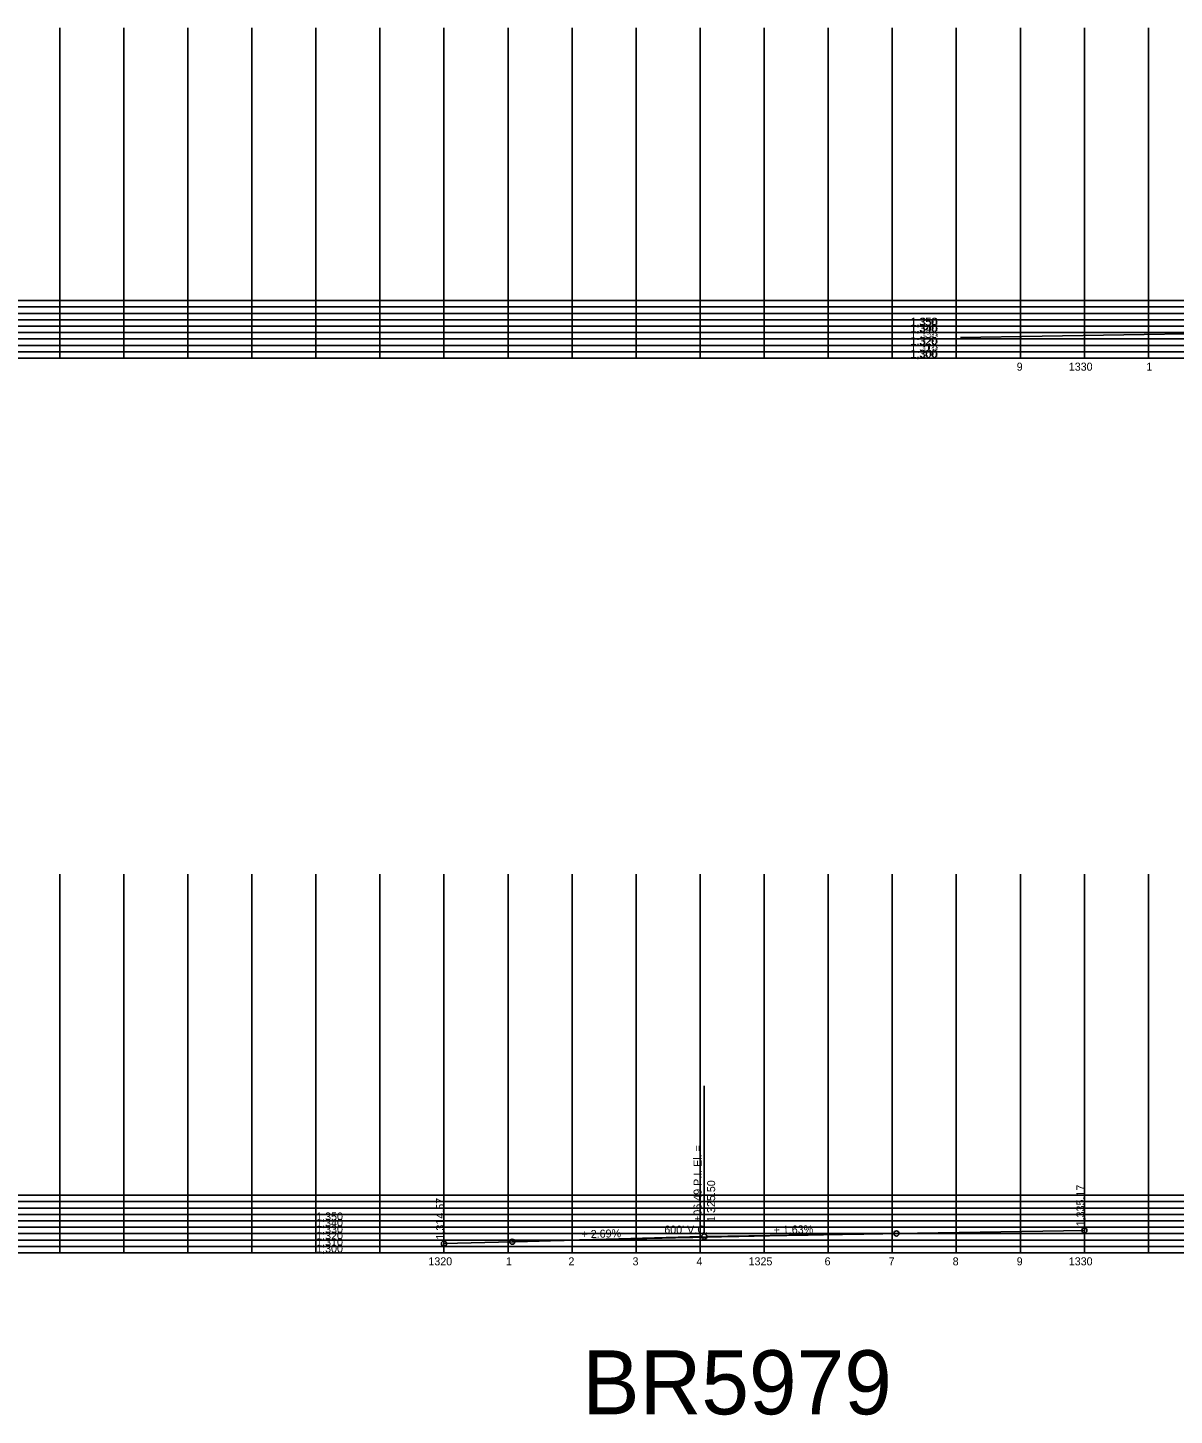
# Model space of a CAD drawing. Extents: x 680639 to 702326, y 743523 to 756592.
# Drawn here: x 687576 to 689366, y 743523 to 745690 of the extents above; entities that cross this region are included whole.
import ezdxf

# ---------------------------------------------------------------- set-up
doc = ezdxf.new("R2010")
doc.units = 0
for name, color, linetype in [('Default', 7, 'Continuous'), ('R_Grid', 7, 'Continuous'), ('R_Proposed Road', 7, 'Continuous')]:
    doc.layers.add(name, color=color, linetype=linetype)

msp = doc.modelspace()

# ---------------------------------------------------------------- linework, layer by layer
at = {"layer": 'Default'}
for p, q in [((689032.2, 745206.1), (689462.2, 745213.1)), ((680725.7, 745174), (702325.7, 745174)), ((688632.2, 743806.2), (688632.2, 744037.6)), ((688225.7, 743791.2), (688332.2, 743794.1)), ((688332.2, 743794.1), (688628.2, 743802)), ((688932.2, 743807), (688636.2, 743802.2)), ((688932.2, 743807), (689225.7, 743811.8)), ((680725.7, 743776.7), (702325.7, 743776.7))]:
    msp.add_line(p, q, dxfattribs=at)
for centre in [(689225.7, 743811.8), (688225.7, 743791.2), (688332.2, 743794.1), (688632.2, 743802.2), (688932.2, 743807)]:
    msp.add_circle(centre, 4, dxfattribs=at)
msp.add_spline([(688332.2, 743794.1), (688344.2, 743794.4), (688356.2, 743794.7), (688368.2, 743795), (688380.2, 743795.4), (688392.2, 743795.7), (688404.2, 743796), (688416.2, 743796.3), (688428.2, 743796.6), (688440.2, 743796.9), (688452.2, 743797.2), (688464.2, 743797.5), (688476.2, 743797.8), (688488.2, 743798.1), (688500.2, 743798.4), (688512.2, 743798.6), (688524.2, 743798.9), (688536.2, 743799.2), (688548.2, 743799.5), (688560.2, 743799.8), (688572.2, 743800), (688584.2, 743800.3), (688596.2, 743800.6), (688608.2, 743800.8), (688620.2, 743801.1), (688632.2, 743801.4), (688644.2, 743801.6), (688656.2, 743801.9), (688668.2, 743802.1), (688680.2, 743802.4), (688692.2, 743802.6), (688704.2, 743802.9), (688716.2, 743803.1), (688728.2, 743803.4), (688740.2, 743803.6), (688752.2, 743803.8), (688764.2, 743804.1), (688776.2, 743804.3), (688788.2, 743804.5), (688800.2, 743804.7), (688812.2, 743805), (688824.2, 743805.2), (688836.2, 743805.4), (688848.2, 743805.6), (688860.2, 743805.8), (688872.2, 743806), (688884.2, 743806.2), (688896.2, 743806.4), (688908.2, 743806.6), (688920.2, 743806.8), (688932.2, 743807)], degree=3, dxfattribs=at)
at = {"layer": 'R_Grid'}
for p, q in [((687625.7, 745174), (687625.7, 745690.1)), ((687725.7, 745174), (687725.7, 745690.1)), ((687825.7, 745174), (687825.7, 745690.1)), ((687925.7, 745174), (687925.7, 745690.1)), ((688025.7, 745174), (688025.7, 745690.1)), ((688125.7, 745174), (688125.7, 745690.1)), ((688225.7, 745174), (688225.7, 745690.1)), ((688325.7, 745174), (688325.7, 745690.1)), ((688425.7, 745174), (688425.7, 745690.1)), ((688525.7, 745174), (688525.7, 745690.1)), ((688625.7, 745174), (688625.7, 745690.1)), ((688725.7, 745174), (688725.7, 745690.1)), ((688825.7, 745174), (688825.7, 745690.1)), ((688925.7, 745174), (688925.7, 745690.1)), ((689025.7, 745174), (689025.7, 745690.1)), ((689125.7, 745174), (689125.7, 745690.1)), ((689225.7, 745174), (689225.7, 745690.1)), ((689325.7, 745174), (689325.7, 745690.1)), ((680725.7, 745264), (695445.5, 745264)), ((680725.7, 745254), (695445.5, 745254)), ((680725.7, 745244), (695445.5, 745244)), ((680725.7, 745234), (695445.5, 745234)), ((680725.7, 745224), (695445.5, 745224)), ((680725.7, 745214), (695445.5, 745214)), ((680725.7, 745204), (695445.5, 745204)), ((680725.7, 745194), (695445.5, 745194)), ((680725.7, 745184), (695445.5, 745184)), ((680725.7, 745174), (695445.5, 745174)), ((687625.7, 743776.7), (687625.7, 744368.3)), ((687725.7, 743776.7), (687725.7, 744368.3)), ((687825.7, 743776.7), (687825.7, 744368.3)), ((687925.7, 743776.7), (687925.7, 744368.3)), ((688025.7, 743776.7), (688025.7, 744368.3)), ((688125.7, 743776.7), (688125.7, 744368.3)), ((688225.7, 743776.7), (688225.7, 744368.3)), ((688325.7, 743776.7), (688325.7, 744368.3)), ((688425.7, 743776.7), (688425.7, 744368.3)), ((688525.7, 743776.7), (688525.7, 744368.3)), ((688625.7, 743776.7), (688625.7, 744368.3)), ((688725.7, 743776.7), (688725.7, 744368.3)), ((688825.7, 743776.7), (688825.7, 744368.3)), ((688925.7, 743776.7), (688925.7, 744368.3)), ((689025.7, 743776.7), (689025.7, 744368.3)), ((689125.7, 743776.7), (689125.7, 744368.3)), ((689225.7, 743776.7), (689225.7, 744368.3)), ((689325.7, 743776.7), (689325.7, 744368.3)), ((680725.7, 743866.7), (694315.6, 743866.7)), ((680725.7, 743856.7), (694315.6, 743856.7)), ((680725.7, 743846.7), (694315.6, 743846.7)), ((680725.7, 743836.7), (694315.6, 743836.7)), ((680725.7, 743826.7), (694315.6, 743826.7)), ((680725.7, 743816.7), (694315.6, 743816.7)), ((680725.7, 743806.7), (694315.6, 743806.7)), ((680725.7, 743796.7), (694315.6, 743796.7)), ((680725.7, 743786.7), (694315.6, 743786.7)), ((680725.7, 743776.7), (694315.6, 743776.7))]:
    msp.add_line(p, q, dxfattribs=at)

# ---------------------------------------------------------------- texts
at = {"layer": 'Default'}
for s, p in [('1,350', (688953.9, 745224.6)), ('1,340', (688953.9, 745214.6)), ('1,350', (688954, 745224.6)), ('1,340', (688954, 745214.6)), ('1,350', (688954.1, 745224.6)), ('1,340', (688954.1, 745214.6)), ('1,350', (688954.2, 745224.6)), ('1,350', (688954.3, 745224.6)), ('1,340', (688954.2, 745214.6)), ('1,340', (688954.3, 745214.6)), ('1,350', (688954.4, 745224.6)), ('1,340', (688954.4, 745214.6)), ('1,350', (688954.4, 745224.6)), ('1,340', (688954.4, 745214.6)), ('1,350', (688954.5, 745224.6)), ('1,340', (688954.5, 745214.6)), ('1,350', (688954.6, 745224.6)), ('1,340', (688954.6, 745214.6)), ('1,350', (688954.7, 745224.6)), ('1,350', (688954.8, 745224.6)), ('1,340', (688954.7, 745214.6)), ('1,340', (688954.8, 745214.6)), ('1,350', (688954.9, 745224.6)), ('1,340', (688954.9, 745214.6)), ('1,350', (688954.9, 745224.6)), ('1,340', (688954.9, 745214.6)), ('1,350', (688955, 745224.6)), ('1,340', (688955, 745214.6)), ('1,350', (688955.1, 745224.6)), ('1,340', (688955.1, 745214.6)), ('1,350', (688955.2, 745224.6)), ('1,350', (688955.3, 745224.6)), ('1,340', (688955.2, 745214.6)), ('1,340', (688955.3, 745214.6)), ('1,350', (688955.4, 745224.6)), ('1,340', (688955.4, 745214.6)), ('1,350', (688955.4, 745224.6)), ('1,340', (688955.4, 745214.6)), ('1,350', (688955.5, 745224.6)), ('1,340', (688955.5, 745214.6)), ('1,330', (688953.9, 745204.6)), ('1,320', (688953.9, 745194.6)), ('1,330', (688954, 745204.6)), ('1,320', (688954, 745194.6)), ('1,330', (688954.1, 745204.6)), ('1,320', (688954.1, 745194.6)), ('1,330', (688954.2, 745204.6)), ('1,330', (688954.3, 745204.6)), ('1,320', (688954.2, 745194.6)), ('1,320', (688954.3, 745194.6)), ('1,330', (688954.4, 745204.6)), ('1,320', (688954.4, 745194.6)), ('1,330', (688954.4, 745204.6)), ('1,320', (688954.4, 745194.6)), ('1,330', (688954.5, 745204.6)), ('1,320', (688954.5, 745194.6)), ('1,330', (688954.6, 745204.6)), ('1,320', (688954.6, 745194.6)), ('1,330', (688954.7, 745204.6)), ('1,330', (688954.8, 745204.6)), ('1,320', (688954.7, 745194.6)), ('1,320', (688954.8, 745194.6)), ('1,330', (688954.9, 745204.6)), ('1,320', (688954.9, 745194.6)), ('1,330', (688954.9, 745204.6)), ('1,320', (688954.9, 745194.6)), ('1,330', (688955, 745204.6)), ('1,320', (688955, 745194.6)), ('1,330', (688955.1, 745204.6)), ('1,320', (688955.1, 745194.6)), ('1,330', (688955.2, 745204.6)), ('1,330', (688955.3, 745204.6)), ('1,320', (688955.2, 745194.6)), ('1,320', (688955.3, 745194.6)), ('1,330', (688955.4, 745204.6)), ('1,320', (688955.4, 745194.6)), ('1,330', (688955.4, 745204.6)), ('1,320', (688955.4, 745194.6)), ('1,330', (688955.5, 745204.6)), ('1,320', (688955.5, 745194.6)), ('1,310', (688953.9, 745184.6)), ('1,300', (688953.9, 745174.6)), ('1,310', (688954, 745184.6)), ('1,300', (688954, 745174.6)), ('1,310', (688954.1, 745184.6)), ('1,300', (688954.1, 745174.6)), ('1,310', (688954.2, 745184.6)), ('1,310', (688954.3, 745184.6)), ('1,300', (688954.2, 745174.6)), ('1,300', (688954.3, 745174.6)), ('1,310', (688954.4, 745184.6)), ('1,300', (688954.4, 745174.6)), ('1,310', (688954.4, 745184.6)), ('1,300', (688954.4, 745174.6)), ('1,310', (688954.5, 745184.6)), ('1,300', (688954.5, 745174.6)), ('1,310', (688954.6, 745184.6)), ('1,300', (688954.6, 745174.6)), ('1,310', (688954.7, 745184.6)), ('1,310', (688954.8, 745184.6)), ('1,300', (688954.7, 745174.6)), ('1,300', (688954.8, 745174.6)), ('1,310', (688954.9, 745184.6)), ('1,300', (688954.9, 745174.6)), ('1,310', (688954.9, 745184.6)), ('1,300', (688954.9, 745174.6)), ('1,310', (688955, 745184.6)), ('1,300', (688955, 745174.6)), ('1,310', (688955.1, 745184.6)), ('1,300', (688955.1, 745174.6)), ('1,310', (688955.2, 745184.6)), ('1,310', (688955.3, 745184.6)), ('1,300', (688955.2, 745174.6)), ('1,300', (688955.3, 745174.6)), ('1,310', (688955.4, 745184.6)), ('1,300', (688955.4, 745174.6)), ('1,310', (688955.4, 745184.6)), ('1,300', (688955.4, 745174.6)), ('1,310', (688955.5, 745184.6)), ('1,300', (688955.5, 745174.6)), ('9', (689120, 745154.5)), ('1330', (689201.3, 745154.5)), ('1', (689322.5, 745154.5)), ('1,350', (688026.1, 743827.3)), ('1,340', (688026.1, 743817.3)), ('1,340', (688026.1, 743817.3)), ('1,330', (688026.1, 743807.3)), ('1,330', (688026.1, 743807.3)), ("600' V.C. ", (688569.7, 743806.8)), ('1,320', (688026.1, 743797.3)), ('1,320', (688026.1, 743797.3)), ('1,310', (688026.1, 743787.3)), ('1,310', (688026.1, 743787.3)), ('1,300', (688026.1, 743777.3)), ('1,300', (688026.1, 743777.3)), ('1320', (688201.3, 743757.2)), ('1', (688322.5, 743757.2)), ('2', (688420, 743757.2)), ('3', (688520.1, 743757.2)), ('4', (688620, 743757.2)), ('1325', (688701.3, 743757.2)), ('6', (688820, 743757.2)), ('7', (688920, 743757.2)), ('8', (689020, 743757.2)), ('9', (689120, 743757.2)), ('1330', (689201.3, 743757.2))]:
    msp.add_text(s, height=12.5, dxfattribs=at).set_placement(p)
for s, rotation, p in [('+06.49 P.I. El. = ', 90, (688627.9, 743825)), ('1,325.50', 90, (688649.1, 743825)), ('1,335.17', 90, (689225.7, 743818.1)), ('1,314.57', 90, (688225.7, 743797.5)), ('+ 2.69%', 1.5409, (688440.6, 743799.5)), ('+ 1.63%', 0.9338, (688740.5, 743806.4))]:
    msp.add_text(s, height=12.5, rotation=rotation, dxfattribs=at).set_placement(p)
at = {"layer": 'R_Proposed Road'}
msp.add_text('BR5979', height=100, dxfattribs=at).set_placement((688441.8, 743524.5))

doc.saveas('drawing.dxf')
